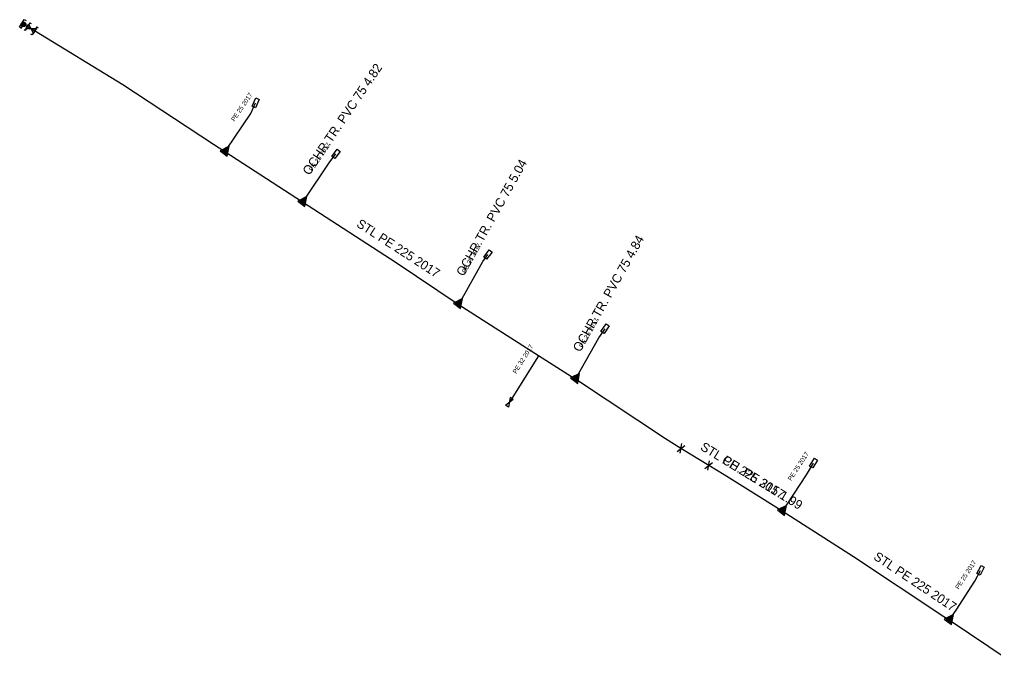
# Model space of a CAD drawing. Extents: x -742724 to -742460, y -1054602 to -1054379.
# Drawn here: x -742723.5 to -742616.2, y -1054551.9 to -1054481.4 of the extents above; entities that cross this region are included whole.
import ezdxf

# ---------------------------------------------------------------- set-up
doc = ezdxf.new("R2010")
doc.units = 0
for name, color, linetype in [('ST OP Chráni_ka - provoz', 7, 'Continuous'), ('ST Úsek p_ípojky - provoz', 7, 'Continuous'), ('ST Úsek plynovodu - provoz', 7, 'Continuous'), ('Vrstva 1', 7, 'Continuous')]:
    doc.layers.add(name, color=color, linetype=linetype)

msp = doc.modelspace()

# ---------------------------------------------------------------- linework, layer by layer
at = {"layer": 'ST OP Chráni_ka - provoz'}
for points in [[(-742700.72, -1054495.69), (-742698.03, -1054491.72)], [(-742692.11, -1054501.15), (-742689.41, -1054497.16)], [(-742674.96, -1054512.4), (-742672.5, -1054508)], [(-742662.08, -1054520.65), (-742659.7, -1054516.43)], [(-742650.66, -1054528.59), (-742652.35, -1054527.52)], [(-742645.9, -1054531.51), (-742647.6, -1054530.47)], [(-742638.93, -1054534.68), (-742636.84, -1054531.48)], [(-742620.35, -1054546.4), (-742618.27, -1054543.21)]]:
    msp.add_lwpolyline(points, dxfattribs=at)
at = {"layer": 'ST Úsek p_ípojky - provoz'}
for points in [[(-742700.74, -1054495.72), (-742700.72, -1054495.69), (-742698.03, -1054491.72), (-742697.52, -1054490.54)], [(-742700.92, -1054495.95), (-742700.74, -1054495.72)], [(-742692.17, -1054501.25), (-742692.11, -1054501.15), (-742689.41, -1054497.16), (-742688.67, -1054496.16)], [(-742692.35, -1054501.49), (-742692.17, -1054501.25)], [(-742675.02, -1054512.49), (-742674.96, -1054512.4), (-742672.5, -1054508), (-742671.93, -1054507.25)], [(-742675.2, -1054512.73), (-742675.02, -1054512.49)], [(-742662.12, -1054520.74), (-742662.08, -1054520.65), (-742659.7, -1054516.43), (-742659.02, -1054515.41)], [(-742666.36, -1054518.38), (-742669.56, -1054523.5)], [(-742662.3, -1054520.97), (-742662.12, -1054520.74)], [(-742639.33, -1054535.26), (-742638.93, -1054534.68), (-742636.84, -1054531.48), (-742636.05, -1054530.21)], [(-742639.51, -1054535.5), (-742639.33, -1054535.26)], [(-742620.95, -1054547.28), (-742620.35, -1054546.4), (-742618.27, -1054543.21), (-742617.66, -1054542.02)], [(-742621.13, -1054547.51), (-742620.95, -1054547.28)]]:
    msp.add_lwpolyline(points, dxfattribs=at)
at = {"layer": 'ST Úsek plynovodu - provoz'}
for points in [[(-742722.65, -1054482.16), (-742723.09, -1054481.9), (-742723.27, -1054481.79)], [(-742722.25, -1054482.4), (-742722.65, -1054482.16)], [(-742721.88, -1054482.62), (-742722.25, -1054482.4)], [(-742652.35, -1054527.52), (-742661.95, -1054521.19), (-742662.3, -1054520.97), (-742666.36, -1054518.38), (-742672.04, -1054514.75), (-742675.2, -1054512.73), (-742682.04, -1054508.17), (-742692.35, -1054501.49), (-742700.92, -1054495.95), (-742702.14, -1054495.14), (-742712.13, -1054488.55), (-742721.88, -1054482.62)], [(-742645.9, -1054531.51), (-742647.6, -1054530.47), (-742650.66, -1054528.59), (-742652.35, -1054527.52)], [(-742614.49, -1054551.94), (-742621.13, -1054547.51), (-742621.72, -1054547.14), (-742631.67, -1054540.51), (-742639.51, -1054535.5), (-742641.78, -1054534.07), (-742645.9, -1054531.51)]]:
    msp.add_lwpolyline(points, dxfattribs=at)
at = {"layer": 'Vrstva 1'}
for p, q in [((-742723.34, -1054482.33), (-742723.09, -1054481.9)), ((-742722.39, -1054481.73), (-742722.9, -1054482.59)), ((-742722.83, -1054482.4), (-742722.52, -1054481.88)), ((-742722.52, -1054481.88), (-742721.98, -1054482.92)), ((-742722.39, -1054481.73), (-742722.26, -1054481.81)), ((-742722.9, -1054482.59), (-742723.03, -1054482.51)), ((-742721.67, -1054482.4), (-742722.83, -1054482.4)), ((-742722.14, -1054483.05), (-742722.27, -1054482.97)), ((-742721.62, -1054482.19), (-742722.14, -1054483.05)), ((-742721.98, -1054482.92), (-742721.67, -1054482.4)), ((-742721.62, -1054482.19), (-742721.49, -1054482.27)), ((-742650.75, -1054529.12), (-742650.57, -1054528.06)), ((-742651.09, -1054528.91), (-742650.23, -1054528.27)), ((-742648.03, -1054530.79), (-742647.17, -1054530.15)), ((-742647.69, -1054531), (-742647.51, -1054529.94))]:
    msp.add_line(p, q, dxfattribs=at)
for points in [[(-742723.32, -1054482.35), (-742723.53, -1054482.22), (-742723.01, -1054481.36), (-742722.8, -1054481.49)], [(-742669.66, -1054524.03), (-742669.99, -1054523.82), (-742669.13, -1054523.18), (-742669.46, -1054522.97), (-742669.66, -1054524.03)]]:
    msp.add_lwpolyline(points, dxfattribs=at)
for points in [[(-742723.21, -1054482.12), (-742723.23, -1054482.11), (-742723.25, -1054482.09), (-742723.27, -1054482.08), (-742723.28, -1054482.06), (-742723.3, -1054482.04), (-742723.31, -1054482.02), (-742723.32, -1054482), (-742723.33, -1054481.97), (-742723.33, -1054481.95), (-742723.34, -1054481.93), (-742723.34, -1054481.9), (-742723.34, -1054481.88), (-742723.34, -1054481.85), (-742723.33, -1054481.83), (-742723.32, -1054481.81), (-742723.31, -1054481.78), (-742723.3, -1054481.76), (-742723.28, -1054481.74), (-742723.27, -1054481.72), (-742723.25, -1054481.71), (-742723.23, -1054481.69), (-742723.21, -1054481.68), (-742723.19, -1054481.67), (-742723.16, -1054481.66), (-742723.14, -1054481.65), (-742723.12, -1054481.65), (-742723.09, -1054481.65), (-742723.07, -1054481.65), (-742723.04, -1054481.65), (-742723.02, -1054481.66), (-742723, -1054481.67), (-742722.97, -1054481.68), (-742722.95, -1054481.69), (-742722.93, -1054481.71), (-742722.91, -1054481.72), (-742722.9, -1054481.74), (-742722.88, -1054481.76), (-742722.87, -1054481.78), (-742722.86, -1054481.8), (-742722.85, -1054481.82), (-742722.84, -1054481.85), (-742722.84, -1054481.87), (-742722.84, -1054481.9), (-742722.84, -1054481.92), (-742722.84, -1054481.95), (-742722.85, -1054481.97), (-742722.86, -1054481.99), (-742722.87, -1054482.02), (-742722.88, -1054482.04), (-742722.9, -1054482.06), (-742722.91, -1054482.08), (-742722.93, -1054482.09), (-742722.95, -1054482.11), (-742722.97, -1054482.12), (-742722.99, -1054482.13), (-742723.01, -1054482.14), (-742723.04, -1054482.14), (-742723.06, -1054482.15), (-742723.09, -1054482.15), (-742723.11, -1054482.15), (-742723.14, -1054482.15), (-742723.16, -1054482.14), (-742723.18, -1054482.13)], [(-742722.93, -1054481.98), (-742722.94, -1054482), (-742722.95, -1054482.01), (-742722.96, -1054482.02), (-742722.98, -1054482.03), (-742722.99, -1054482.05), (-742723.01, -1054482.05), (-742723.02, -1054482.06), (-742723.04, -1054482.07), (-742723.05, -1054482.07), (-742723.07, -1054482.07), (-742723.09, -1054482.07), (-742723.11, -1054482.07), (-742723.12, -1054482.07), (-742723.14, -1054482.07), (-742723.16, -1054482.06), (-742723.17, -1054482.06), (-742723.19, -1054482.05), (-742723.2, -1054482.04), (-742723.21, -1054482.03), (-742723.22, -1054482.01), (-742723.23, -1054482), (-742723.24, -1054481.98), (-742723.25, -1054481.97), (-742723.26, -1054481.95), (-742723.26, -1054481.93), (-742723.26, -1054481.92), (-742723.26, -1054481.9), (-742723.26, -1054481.88), (-742723.26, -1054481.87), (-742723.26, -1054481.85), (-742723.25, -1054481.83), (-742723.24, -1054481.82), (-742723.24, -1054481.8), (-742723.23, -1054481.79), (-742723.21, -1054481.78), (-742723.2, -1054481.77), (-742723.19, -1054481.76), (-742723.17, -1054481.75), (-742723.16, -1054481.74), (-742723.14, -1054481.73), (-742723.12, -1054481.73), (-742723.11, -1054481.73), (-742723.09, -1054481.72), (-742723.07, -1054481.72), (-742723.06, -1054481.73), (-742723.04, -1054481.73), (-742723.02, -1054481.74), (-742723.01, -1054481.75), (-742722.99, -1054481.75), (-742722.98, -1054481.76), (-742722.97, -1054481.78), (-742722.96, -1054481.79), (-742722.94, -1054481.8), (-742722.94, -1054481.82), (-742722.93, -1054481.83), (-742722.92, -1054481.85), (-742722.92, -1054481.86), (-742722.92, -1054481.88), (-742722.92, -1054481.9), (-742722.91, -1054481.92), (-742722.92, -1054481.93), (-742722.92, -1054481.95), (-742722.93, -1054481.97)], [(-742723.22, -1054481.83), (-742723.22, -1054481.82), (-742723.21, -1054481.81), (-742723.2, -1054481.79), (-742723.19, -1054481.78), (-742723.17, -1054481.78), (-742723.16, -1054481.77), (-742723.15, -1054481.76), (-742723.13, -1054481.76), (-742723.12, -1054481.75), (-742723.11, -1054481.75), (-742723.09, -1054481.75), (-742723.08, -1054481.75), (-742723.06, -1054481.75), (-742723.05, -1054481.76), (-742723.03, -1054481.76), (-742723.02, -1054481.77), (-742723.01, -1054481.77), (-742723, -1054481.78), (-742722.98, -1054481.79), (-742722.97, -1054481.8), (-742722.97, -1054481.82), (-742722.96, -1054481.83), (-742722.95, -1054481.84), (-742722.95, -1054481.86), (-742722.94, -1054481.87), (-742722.94, -1054481.88), (-742722.94, -1054481.9), (-742722.94, -1054481.91), (-742722.94, -1054481.93), (-742722.95, -1054481.94), (-742722.95, -1054481.96), (-742722.96, -1054481.97), (-742722.96, -1054481.98), (-742722.97, -1054481.99), (-742722.98, -1054482.01), (-742722.99, -1054482.02), (-742723.01, -1054482.02), (-742723.02, -1054482.03), (-742723.03, -1054482.04), (-742723.04, -1054482.04), (-742723.06, -1054482.05), (-742723.07, -1054482.05), (-742723.09, -1054482.05), (-742723.1, -1054482.05), (-742723.12, -1054482.05), (-742723.13, -1054482.04), (-742723.15, -1054482.04), (-742723.16, -1054482.03), (-742723.17, -1054482.03), (-742723.18, -1054482.02), (-742723.19, -1054482.01), (-742723.2, -1054482), (-742723.21, -1054481.98), (-742723.22, -1054481.97), (-742723.23, -1054481.96), (-742723.23, -1054481.94), (-742723.24, -1054481.93), (-742723.24, -1054481.92), (-742723.24, -1054481.9), (-742723.24, -1054481.89), (-742723.24, -1054481.87), (-742723.23, -1054481.86), (-742723.23, -1054481.84)], [(-742723.16, -1054481.86), (-742723.15, -1054481.86), (-742723.15, -1054481.85), (-742723.14, -1054481.85), (-742723.14, -1054481.84), (-742723.13, -1054481.84), (-742723.13, -1054481.83), (-742723.12, -1054481.83), (-742723.11, -1054481.83), (-742723.1, -1054481.83), (-742723.1, -1054481.82), (-742723.09, -1054481.82), (-742723.08, -1054481.83), (-742723.08, -1054481.83), (-742723.07, -1054481.83), (-742723.06, -1054481.83), (-742723.06, -1054481.83), (-742723.05, -1054481.84), (-742723.04, -1054481.84), (-742723.04, -1054481.85), (-742723.03, -1054481.85), (-742723.03, -1054481.86), (-742723.02, -1054481.86), (-742723.02, -1054481.87), (-742723.02, -1054481.88), (-742723.02, -1054481.88), (-742723.02, -1054481.89), (-742723.01, -1054481.9), (-742723.02, -1054481.91), (-742723.02, -1054481.91), (-742723.02, -1054481.92), (-742723.02, -1054481.93), (-742723.02, -1054481.93), (-742723.03, -1054481.94), (-742723.03, -1054481.95), (-742723.04, -1054481.95), (-742723.04, -1054481.96), (-742723.05, -1054481.96), (-742723.05, -1054481.97), (-742723.06, -1054481.97), (-742723.07, -1054481.97), (-742723.07, -1054481.97), (-742723.08, -1054481.97), (-742723.09, -1054481.97), (-742723.1, -1054481.97), (-742723.1, -1054481.97), (-742723.11, -1054481.97), (-742723.12, -1054481.97), (-742723.12, -1054481.97), (-742723.13, -1054481.96), (-742723.14, -1054481.96), (-742723.14, -1054481.95), (-742723.15, -1054481.95), (-742723.15, -1054481.94), (-742723.16, -1054481.94), (-742723.16, -1054481.93), (-742723.16, -1054481.92), (-742723.16, -1054481.92), (-742723.16, -1054481.91), (-742723.16, -1054481.9), (-742723.16, -1054481.89), (-742723.16, -1054481.89), (-742723.16, -1054481.88), (-742723.16, -1054481.87)], [(-742697.51, -1054490), (-742697.14, -1054490.16), (-742697.54, -1054491.08), (-742697.9, -1054490.92)], [(-742701.44, -1054495.81), (-742700.65, -1054496.42), (-742700.43, -1054495.32)], [(-742700.72, -1054496.24), (-742700.57, -1054495.5), (-742701.25, -1054495.83)], [(-742700.71, -1054495.68), (-742701.06, -1054495.85), (-742700.78, -1054496.06)], [(-742688.53, -1054495.64), (-742688.21, -1054495.88), (-742688.8, -1054496.68), (-742689.12, -1054496.44)], [(-742692.87, -1054501.35), (-742692.08, -1054501.96), (-742691.87, -1054500.86)], [(-742692.15, -1054501.78), (-742692, -1054501.04), (-742692.68, -1054501.37)], [(-742692.14, -1054501.21), (-742692.49, -1054501.39), (-742692.21, -1054501.6)], [(-742671.78, -1054506.74), (-742671.46, -1054506.98), (-742672.07, -1054507.77), (-742672.39, -1054507.53)], [(-742675.73, -1054512.58), (-742674.93, -1054513.19), (-742674.72, -1054512.1)], [(-742675, -1054513.02), (-742674.86, -1054512.27), (-742675.54, -1054512.6)], [(-742674.99, -1054512.45), (-742675.35, -1054512.62), (-742675.07, -1054512.84)], [(-742658.91, -1054514.88), (-742658.58, -1054515.11), (-742659.13, -1054515.94), (-742659.47, -1054515.72)], [(-742662.82, -1054520.83), (-742662.03, -1054521.44), (-742661.82, -1054520.34)], [(-742662.1, -1054521.26), (-742661.95, -1054520.52), (-742662.63, -1054520.85)], [(-742662.09, -1054520.7), (-742662.44, -1054520.87), (-742662.16, -1054521.09)], [(-742635.96, -1054529.68), (-742635.62, -1054529.89), (-742636.15, -1054530.74), (-742636.49, -1054530.53)], [(-742640.03, -1054535.35), (-742639.24, -1054535.97), (-742639.02, -1054534.87)], [(-742639.3, -1054535.79), (-742639.16, -1054535.05), (-742639.84, -1054535.37)], [(-742639.29, -1054535.22), (-742639.65, -1054535.39), (-742639.37, -1054535.61)], [(-742617.6, -1054541.48), (-742617.25, -1054541.66), (-742617.71, -1054542.55), (-742618.06, -1054542.37)], [(-742621.65, -1054547.37), (-742620.86, -1054547.98), (-742620.64, -1054546.88)], [(-742620.93, -1054547.8), (-742620.78, -1054547.06), (-742621.46, -1054547.39)], [(-742620.92, -1054547.24), (-742621.27, -1054547.41), (-742620.99, -1054547.62)]]:
    msp.add_lwpolyline(points, close=True, dxfattribs=at)

# ---------------------------------------------------------------- texts
at = {"layer": 'ST OP Chráni_ka - provoz'}
for s, rotation, p in [('OCHR.TR. PVC 75 4.82', 55.9141, (-742691.59, -1054498.59)), ('OCHR.TR. PVC 75 5.04', 60.7908, (-742674.6, -1054509.71)), ('OCHR.TR. PVC 75 4.84', 60.5778, (-742661.76, -1054518.05)), ('CH. PE 315 1.99', 328.5432, (-742646.23, -1054530.14))]:
    msp.add_text(s, height=1, rotation=rotation, dxfattribs=at).set_placement(p)
at = {"layer": 'ST Úsek p_ípojky - provoz'}
for s, rotation, p in [('PE 25 2017', 55.8791, (-742699.85, -1054492.63)), ('PE 25 2017', 55.9141, (-742691.27, -1054498.13)), ('PE 25 2017', 60.7908, (-742674.4, -1054509.35)), ('PE 25 2017', 60.5778, (-742661.48, -1054517.56)), ('PE 32 2017', 57.9996, (-742668.81, -1054520.41)), ('PE 25 2017', 56.8504, (-742638.51, -1054532.2)), ('PE 25 2017', 56.8941, (-742620.07, -1054544.14))]:
    msp.add_text(s, height=0.5, rotation=rotation, dxfattribs=at).set_placement(p)
at = {"layer": 'ST Úsek plynovodu - provoz'}
for rotation, p in [(327.0524, (-742686.49, -1054504.1)), (328.4343, (-742648.61, -1054528.68)), (326.3232, (-742629.53, -1054540.73))]:
    msp.add_text('STL PE 225 2017', height=1, rotation=rotation, dxfattribs=at).set_placement(p)

doc.saveas('drawing.dxf')
